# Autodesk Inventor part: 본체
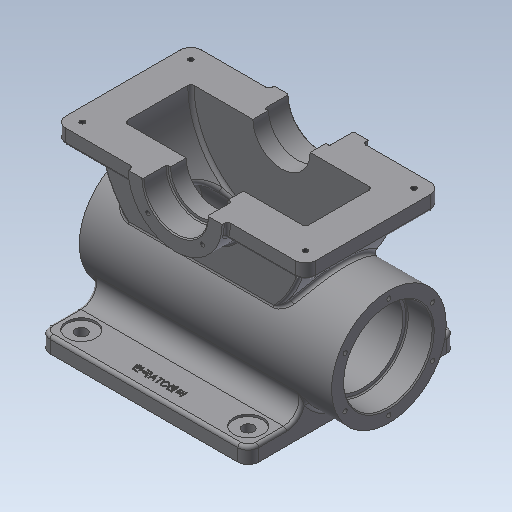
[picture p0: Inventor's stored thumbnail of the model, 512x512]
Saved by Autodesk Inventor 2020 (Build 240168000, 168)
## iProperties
Created: 2023-06
Part Number: 본체
Material: 일반
Document SubType Name: Modeling
Designer: mdu-01
Mass: 5644.39 g
Surface Area: 2847.06 cm^2
Volume: 2082.8 cm^3
Density: 2.71 g/cm^3
Appearance: 기본값
Author: mdu-01
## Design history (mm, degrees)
sketch "스케치1"
  geometry: L1 (0, 70)-(0, -70); L2 (0, 0)-(-100, 0); L3 (0, 70)-(-45, 70); L4 (-45, 70)-(-45, 45); L5 (-45, 45)-(-100, 45); L6 (0, -70)-(-45, -70); L7 (-45, -70)-(-45, -45); L8 (-45, -45)-(-100, -45); L9 (-100, 45)-(-100, -45); 1 further point
  constraints: 18 end point, 3 perpendicular, 3 symmetric about line, 2 midpoint, 2 parallel, 1 coincident, 1 vertical
  dimensions: "d0" = 140 distance of L1.start L1.end; "d1" = 100 distance of L2.start L2.end; "d3" = 90 diameter of L4 L1; "d4" = 90 distance between parallel lines of L8 L5
revolve "회전1" sketch "스케치1" stored, may be unused: angle "d5" = 180 deg
sketch "스케치2"
  geometry: L1 (-155, -20)-(65, -20); L2 (75, -10)-(75, 100); L3 (65, 110)-(-155, 110); L4 (-165, 100)-(-165, -10); L5 (-165, -20)-(75, 110); L6 (75, -20)-(-165, 110); A1 r 10 centre (-155, 100) between (-155, 110) and (-165, 100); A2 r 10 centre (65, 100) between (75, 100) and (65, 110); A3 r 10 centre (65, -10) between (65, -20) and (75, -10); A4 r 10 centre (-155, -10) between (-165, -10) and (-155, -20); 1 further point
  constraints: 12 end point, 8 point on circle, 8 point on line, 8 tangent, 4 centre point, 3 equal radius, 2 midpoint, 2 parallel, 1 horizontal, 1 perpendicular
  dimensions: "d6" = 240 distance of L6.end L5.end; "d7" = 130 distance of L5.end L6.start; "d8" = 10 radius of A1
extrude "돌출1" join sketch "스케치2" distance "d9" = 15; taper "d10" = 0 deg
sketch "스케치3"
  geometry: C1 r 55 at (-100, 0); 1 further point
  constraints: 1 centre point
  dimensions: "d11" = 110 diameter of C1; "d12" = 100 distance of C1.centre point (0, 0)
extrude "돌출2" join sketch "스케치3" distance "d13" = 135; taper "d15" = 0 deg; dims "d14" = 107, "d16" = 0
sketch "스케치4"
  geometry: L1 (-100, -160)-(100, -160); L2 (100, -160)-(100, -145); L3 (100, -145)-(-100, -145); L4 (-100, -145)-(-100, -160); 1 further point
  constraints: 8 end point, 2 parallel, 1 horizontal, 1 perpendicular
  dimensions: "d17" = 200 distance of L3.end L2.end; "d18" = 15 distance of L2.end L1.end; "d19" = 100 distance from line of L4 point (0, 0); "d20" = 160 distance from line of L1 point (0, 0)
extrude "돌출3" join sketch "스케치4" stored distance "d21" = 200; taper "d22" = 0 deg
fillet "모깎기1" dims "d23" = 15
fillet "모깎기2" dims "d24" = 10
sketch "스케치5"
  geometry: L1 (0, 70)-(0, -70); L2 (-45, 70)-(0, 70) reference; L3 (-45, -70)-(0, -70) reference; L4 (-31, 70)-(-31, 48); L5 (-30, 47)-(-27.5, 47); L6 (-27.5, 47)-(-27.5, 32); L7 (-27.5, 32)-(-87, 32); L8 (0, 0)-(-91.923, 0); L9 (-31, -70)-(-31, -48); L10 (-30, -47)-(-27.5, -47); L11 (-27.5, -47)-(-27.5, -32); L12 (-27.5, -32)-(-87, -32); L13 (-87, 32)-(-87, -32); L14 (-31, 70)-(0, 70); L15 (-31, -70)-(0, -70); A1 r 1 centre (-30, 48) between (-31, 48) and (-30, 47); A2 r 1 centre (-30, -48) between (-30, -47) and (-31, -48)
  constraints: 26 end point, 7 symmetric about line, 4 parallel, 4 point on circle, 3 perpendicular, 2 centre point, 2 tangent, 1 collinear, 1 point on line, 1 vertical, 1 other
  dimensions: "d25" = 1 radius of A1; "d26" = 62 diameter of L4 L1; "d27" = 23 distance between parallel lines of L2 L5; "d28" = 64 distance between parallel lines of L12 L7; "d29" = 55 diameter of L6 L1; "d30" = 87 distance between parallel lines of L13 L1
revolve "회전2" sketch "스케치5" stored, may be unused: angle "d31" = 180 deg
sketch "스케치6"
  geometry: L1 (-107, -45)-(-107, -155) reference; L2 (135, -155)-(135, -45) reference; L3 (-107, -100)-(135, -100); L4 (-107, -142.5)-(-83.1, -142.5); L5 (-82, -141.4)-(-82, -138.5); L6 (-82, -138.5)-(110, -138.5); L7 (110, -138.5)-(110, -141.4); L8 (111.1, -142.5)-(135, -142.5); A1 r 1.1 centre (-83.1, -141.4) between (-83.1, -142.5) and (-82, -141.4); A2 r 1.1 centre (111.1, -141.4) between (110, -141.4) and (111.1, -142.5); 1 further point
  constraints: 12 end point, 4 point on circle, 4 tangent, 3 parallel, 2 centre point, 2 collinear, 2 midpoint, 2 perpendicular, 2 point on line, 1 equal radius
  dimensions: "d32" = 1.1 radius of A1; "d33" = 25 distance between parallel lines of L5 L1; "d34" = 77 diameter of L6 L3; "d35" = 85 diameter of L4 L3
revolve "회전3" sketch "스케치6" stored, may be unused: angle "d36" = 180 deg
fillet "모깎기3" dims "d37" = 3
fillet "모깎기4" dims "d38" = 3
sketch "스케치7"
  geometry: L1 (17, -16.754)-(177, -16.754); L2 (177, -16.754)-(177, 143.246); L3 (177, 143.246)-(17, 143.246); L4 (17, 143.246)-(17, -16.754); L5 (17, -16.754)-(177, 143.246); L6 (177, -16.754)-(17, 143.246); 1 further point
  constraints: 12 end point, 2 midpoint, 2 parallel, 1 horizontal, 1 perpendicular
  dimensions: "d39" = 160 distance of L3.end L2.end; "d40" = 160 distance of L2.end L1.end
hole "구멍1" sketch "스케치7" at (17, -16.754), (177, -16.754), (177, 143.246), (17, 143.246) diameter "d41" = 11; stored, may be unused: countersink angle "d45" = 90 deg, drill point angle "d47" = 118 deg; dims "d42" = 6, "d43" = 28, "d44" = 2, "d46" = 8
sketch "스케치8"
  geometry: L1 (-227, 3)-(-13, 3); L2 (-13, 3)-(-13, 107); L3 (-13, 107)-(-227, 107); L4 (-227, 107)-(-227, 3); L5 (-227, 3)-(-13, 107); L6 (-13, 3)-(-227, 107); 1 further point
  constraints: 12 end point, 2 midpoint, 2 parallel, 1 horizontal, 1 perpendicular
  dimensions: "d48" = 214 distance of L3.end L2.end; "d49" = 104 distance of L2.end L1.end
hole "구멍2" sketch "스케치8" at (-227, 3), (-13, 3), (-13, 107), (-227, 107) diameter "d50" = 4.917; stored, may be unused: countersink angle "d54" = 90 deg, drill point angle "d56" = 118 deg; dims "d51" = 15, "d52" = 4, "d53" = 7.5, "d55" = 15
sketch "스케치9"
  geometry: A1 r 37 centre (0, 0) between (-26.163, -26.163) and (26.163, -26.163); 1 further point
  constraints: 2 point on circle, 1 centre point, 1 coincident, 1 horizontal alignment
  dimensions: "d57" = 37 radius of A1; "d58" = 90 deg dimension on A1.centre A1.end A1.start
hole "구멍3" sketch "스케치9" at (-26.163, -26.163), (26.163, -26.163) diameter "d60" = 4.134; stored, may be unused: countersink angle "d64" = 90 deg, drill point angle "d66" = 118 deg; dims "d61" = 10, "d62" = 4, "d63" = 7.5, "d65" = 12
sketch "스케치10" dims "d68" = 97
  geometry: C1 r 38.5 at (0, 0) reference; 3 further points
  constraints: 2 vertical alignment, 1 coincident, 2 other
hole "구멍4" sketch "스케치10" at (0, 48.5) diameter "d70" = 4.134; stored, may be unused: countersink angle "d74" = 90 deg, drill point angle "d76" = 118 deg; dims "d71" = 10, "d72" = 4, "d73" = 7.5, "d75" = 12
node "작업 평면1"
sketch "스케치11"
  geometry: L1 (7, -36.754)-(187, -36.754) reference; 2 further points
  constraints: 1 vertical alignment, 1 other
  dimensions: "d80" = 15 distance from line of point (97, -21.754) L1
feature "엠보싱1" sketch "스케치11" dims "d6" = 240, "d7" = 130, "d8" = 10, "d81" = 0.5, "d82" = 0
chamfer "모따기1" distance "d83" = 1; stored, may be unused: second distance "d84" = 2, angle "d85" = 45 deg
node "솔리드1"
mirror "대칭1"
pattern_circular "원형 패턴1" dims angle "d78" = 360 deg
mirror "대칭2"
